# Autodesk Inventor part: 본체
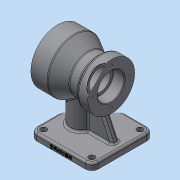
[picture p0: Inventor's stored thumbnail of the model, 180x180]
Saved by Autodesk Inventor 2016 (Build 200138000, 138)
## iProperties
Created: 2019-01
Part Number: 본체
Material: 일반
Document SubType Name: Modeling
Designer: Administrator
Density: 1 g/cm^3
Appearance: 기본값
Author: Administrator
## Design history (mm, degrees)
sketch "스케치1"
  geometry: L1 (0, 0)-(-80, 0); L2 (0, 0)-(0, 40); L3 (0, 40)-(-25, 40); L4 (-25, 40)-(-45.785, 28); L5 (-65, 35)-(-80, 35); L6 (-80, 35)-(-80, 0); L7 (-45.785, 28)-(-59.126, 28); L8 (-59.126, 28)-(-65, 35); L9 (0, 0)-(-80, 0)
  constraints: 18 end point, 3 horizontal, 2 perpendicular, 1 parallel, 1 vertical
  dimensions: "d0" = 80 distance of L1.start L1.end; "d1" = 40 distance of L1.start L2.end; "d2" = 25 distance of L2.end L3.end; "d3" = 15 distance of L5.start L5.end; "d5" = 30 deg angle of L7 L4; "d6" = 50 deg angle of L8 L7; "d7" = 28 distance between parallel lines of L1 L7; "d8" = 35 distance between parallel lines of L5 L1
revolve "회전1" sketch "스케치1" stored, may be unused: angle "d9" = 90 deg
sketch "스케치2"
  geometry: L1 (0, 0)-(-80, 0); L2 (-80, -35)-(-80, 35) reference; L3 (0, 0)-(0, 26); L4 (0, -40)-(0, 40) reference; L5 (0, 26)-(-20, 26); L6 (-20, 26)-(-20, 16); L7 (-20, 16)-(-63, 16); L8 (-63, 16)-(-63, 20); L9 (-63, 20)-(-80, 20); L10 (-80, 20)-(-80, 0); L11 (0, 0)-(-80, 0)
  constraints: 18 end point, 6 perpendicular, 2 point on line, 1 collinear, 1 midpoint
  dimensions: "d10" = 26 distance of L1.start L3.end; "d11" = 20 distance of L3.end L5.end; "d12" = 17 distance of L8.end L9.end; "d13" = 16 distance between parallel lines of L7 L1; "d14" = 20 distance between parallel lines of L1 L9
revolve "회전2" sketch "스케치2" stored, may be unused: angle "d15" = 90 deg
node "작업 평면1"
sketch "스케치3"
  geometry: L1 (0, 0)-(5, 0); L2 (5, 46)-(97, 46); L3 (97, 46)-(97, -46); L4 (97, -46)-(5, -46); L5 (5, -46)-(5, 46)
  constraints: 10 end point, 2 horizontal, 2 parallel, 1 midpoint, 1 perpendicular
  dimensions: "d17" = 5 distance of L1.end L1.start; "d18" = 92 distance of L3.end L4.end; "d19" = 92 distance of L2.end L3.end
extrude "돌출1" join sketch "스케치3" distance "d20" = 10; taper "d21" = 0 deg
sketch "스케치4"
  geometry: L1 (5, -46)-(5, 46) reference; L2 (5, 46)-(97, 46) reference; C1 r 16 at (35, 0); 1 further point
  constraints: 1 centre point
  dimensions: "d22" = 32 diameter of C1; "d23" = 30 distance from line of L1 C1.centre; "d24" = 46 distance from line of L2 C1.centre
extrude "돌출2" join sketch "스케치4" stored distance "d25" = 10; taper "d26" = 0 deg
sketch "스케치5"
  geometry: L1 (-5, -70)-(-97, -70) reference; L2 (-87, -70)-(-70.679, -35); L3 (-80, -35)-(-65, -35) reference; L4 (-97, -80)-(-97, -70) reference; 1 further point
  constraints: 2 end point, 2 point on line
  dimensions: "d27" = 10 distance from line of L2.start L4; "d28" = 25 deg angle of L2 L4
feature "리브1" sketch "스케치5" dims "d29" = 1, "d30" = 10, "d31" = 0, "d32" = 0, "d33" = 1, "d34" = 1
sketch "스케치6"
  geometry: L1 (0, 0)-(33, 0)
  constraints: 2 end point, 1 horizontal
  dimensions: "d35" = 33 distance of L1.start L1.end
hole "구멍1" sketch "스케치6" at (33, 0) diameter "d36" = 3.242; stored, may be unused: countersink angle "d40" = 90 deg, drill point angle "d42" = 118 deg; dims "d37" = 9, "d38" = 4, "d39" = 2, "d41" = 11
sketch "스케치7"
  geometry: L1 (0, 0)-(-27.5, 0)
  constraints: 2 end point, 1 horizontal
  dimensions: "d46" = 27.5 distance of L1.start L1.end
hole "구멍2" sketch "스케치7" at (-27.5, 0) diameter "d47" = 3.242; stored, may be unused: countersink angle "d51" = 90 deg, drill point angle "d53" = 118 deg; dims "d48" = 9, "d49" = 4, "d50" = 2, "d52" = 11
fillet "모깎기1" dims "d57" = 10
hole "구멍3" diameter "d60" = 9; stored, may be unused: countersink angle "d64" = 90 deg, drill point angle "d66" = 118 deg; dims "d58" = 10, "d59" = 10, "d61" = 9, "d62" = 4, "d63" = 2, "d65" = 11
sketch "스케치9"
  geometry: L1 (-10, 10)-(-10, 0) reference; L2 (82, 0)-(72, 0) reference; 2 further points
  constraints: 1 other
  dimensions: "d73" = 46 distance from line of L1 point (36, 4); "d74" = 4 distance from line of point (36, 4) L2
feature "엠보싱1" sketch "스케치9" dims "d10" = 26, "d11" = 20, "d12" = 17, "d13" = 16, "d14" = 20, "d75" = 0.5, "d76" = 0
fillet "모깎기2" dims "d77" = 1
fillet "모깎기3" dims "d78" = 0.6
chamfer "모따기1" distance "d79" = 1; stored, may be unused: second distance "d80" = 2, angle "d81" = 45 deg
fillet "모깎기4" dims "d82" = 3
fillet "모깎기5" dims "d83" = 3
fillet "모깎기6" dims "d84" = 3
fillet "모깎기8" dims "d86" = 3
fillet "모깎기9" dims "d87" = 3
feature "분할1"
node "솔리드1"
pattern_circular "원형 패턴1" dims angle "d44" = 360 deg
pattern_circular "원형 패턴2" dims angle "d55" = 360 deg
pattern_linear "직사각형 패턴1" dims "d69" = 72, "d72" = 72
